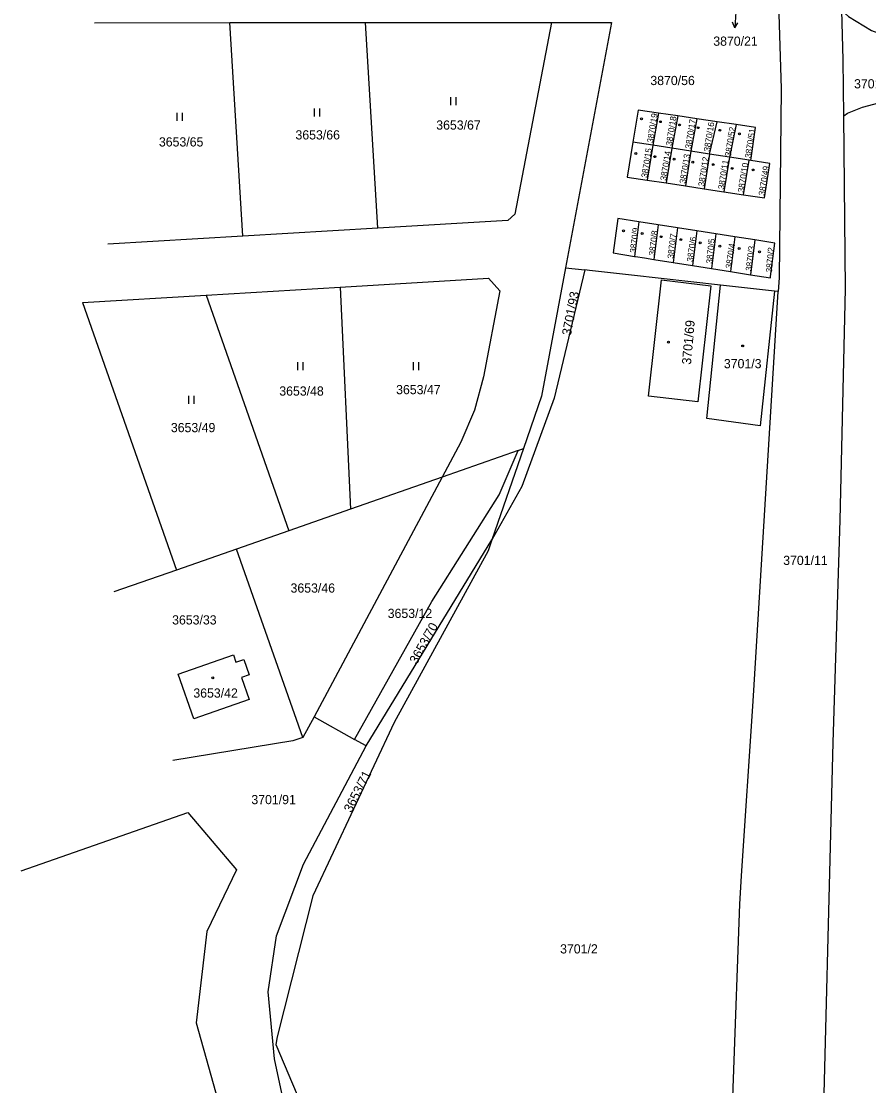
# Model space of a CAD drawing. Extents: x -527335 to -526256, y -1079142 to -1077836.
# Drawn here: x -527299.2 to -527142.6, y -1078182.5 to -1077985.7 of the extents above; entities that cross this region are included whole.
import ezdxf

# ---------------------------------------------------------------- set-up
doc = ezdxf.new("R2010")
doc.units = 0
for name, color, linetype in [('Hranice parcel', 7, 'Continuous'), ('Parcelní čísla', 7, 'Continuous'), ('Pop  PČ popisy', 7, 'Continuous'), ('Značky budov', 7, 'Continuous'), ('Značky kultur', 7, 'Continuous')]:
    doc.layers.add(name, color=color, linetype=linetype)

msp = doc.modelspace()

# ---------------------------------------------------------------- linework, layer by layer
at = {"layer": 'Hranice parcel'}
for p, q in [((-527285.69, -1077985.99), (-527260.64, -1077985.98)), ((-527260.64, -1077985.98), (-527235.6, -1077985.97)), ((-527258.27, -1078025.45), (-527260.64, -1077985.98)), ((-527235.6, -1077985.97), (-527201.2, -1077985.95)), ((-527233.32, -1078023.96), (-527235.6, -1077985.97)), ((-527201.2, -1077985.95), (-527208.02, -1078021.38)), ((-527201.2, -1077985.95), (-527190.13, -1077985.95)), ((-527190.13, -1077985.95), (-527198.62, -1078031.28)), ((-527181.44, -1078002.7), (-527182.49, -1078008.63)), ((-527177.88, -1078003.23), (-527181.44, -1078002.7)), ((-527177.88, -1078003.23), (-527179, -1078009.17)), ((-527174.36, -1078003.75), (-527177.88, -1078003.23)), ((-527174.36, -1078003.75), (-527175.45, -1078009.72)), ((-527170.64, -1078004.32), (-527174.36, -1078003.75)), ((-527172, -1078010.26), (-527170.64, -1078004.32)), ((-527167.08, -1078004.82), (-527170.64, -1078004.32)), ((-527167.08, -1078004.82), (-527168.36, -1078010.83)), ((-527182.49, -1078008.63), (-527186.19, -1078008.06)), ((-527182.49, -1078008.63), (-527183.55, -1078015.08)), ((-527179, -1078009.17), (-527182.49, -1078008.63)), ((-527179, -1078009.17), (-527180.04, -1078015.61)), ((-527175.45, -1078009.72), (-527179, -1078009.17)), ((-527175.45, -1078009.72), (-527176.48, -1078016.15)), ((-527172, -1078010.26), (-527175.45, -1078009.72)), ((-527172, -1078010.26), (-527173.03, -1078016.68)), ((-527168.36, -1078010.83), (-527172, -1078010.26)), ((-527168.36, -1078010.83), (-527169.37, -1078017.23)), ((-527164.72, -1078011.39), (-527168.36, -1078010.83)), ((-527165.72, -1078017.79), (-527164.72, -1078011.39)), ((-527164.4, -1078011.44), (-527164.72, -1078011.39)), ((-527183.55, -1078015.08), (-527180.04, -1078015.61)), ((-527180.04, -1078015.61), (-527176.48, -1078016.15)), ((-527176.48, -1078016.15), (-527173.03, -1078016.68)), ((-527173.03, -1078016.68), (-527169.37, -1078017.23)), ((-527169.37, -1078017.23), (-527165.72, -1078017.79)), ((-527185.08, -1078022.81), (-527185.88, -1078029.17)), ((-527181.52, -1078023.36), (-527185.08, -1078022.81)), ((-527233.32, -1078023.96), (-527258.27, -1078025.45)), ((-527181.52, -1078023.36), (-527182.33, -1078029.74)), ((-527177.96, -1078023.92), (-527181.52, -1078023.36)), ((-527177.96, -1078023.92), (-527178.77, -1078030.3)), ((-527174.39, -1078024.47), (-527177.96, -1078023.92)), ((-527174.39, -1078024.47), (-527175.2, -1078030.87)), ((-527170.84, -1078025.02), (-527174.39, -1078024.47)), ((-527170.84, -1078025.02), (-527171.65, -1078031.43)), ((-527167.33, -1078025.57), (-527170.84, -1078025.02)), ((-527258.27, -1078025.45), (-527283.23, -1078026.95)), ((-527167.33, -1078025.57), (-527168.15, -1078031.98)), ((-527163.67, -1078026.14), (-527167.33, -1078025.57)), ((-527163.67, -1078026.14), (-527164.48, -1078032.56)), ((-527182.33, -1078029.74), (-527178.77, -1078030.3)), ((-527178.77, -1078030.3), (-527175.2, -1078030.87)), ((-527175.2, -1078030.87), (-527171.65, -1078031.43)), ((-527198.62, -1078031.28), (-527195.06, -1078031.68)), ((-527171.65, -1078031.43), (-527168.15, -1078031.98)), ((-527168.15, -1078031.98), (-527164.48, -1078032.56)), ((-527265.02, -1078036.33), (-527240.25, -1078034.84)), ((-527240.25, -1078034.84), (-527238.34, -1078075.88)), ((-527160.02, -1078035.61), (-527169.98, -1078034.5)), ((-527287.85, -1078037.7), (-527265.02, -1078036.33)), ((-527265.02, -1078036.33), (-527249.76, -1078079.88)), ((-527159.33, -1078035.65), (-527160.02, -1078035.61)), ((-527287.85, -1078037.7), (-527270.53, -1078087.15)), ((-527207.36, -1078065.03), (-527221.44, -1078069.96)), ((-527206.41, -1078064.7), (-527212.24, -1078081.56)), ((-527207.36, -1078065.03), (-527206.41, -1078064.7)), ((-527221.44, -1078069.96), (-527245.09, -1078114.25)), ((-527221.44, -1078069.96), (-527238.34, -1078075.88)), ((-527238.34, -1078075.88), (-527249.76, -1078079.88)), ((-527249.76, -1078079.88), (-527259.42, -1078083.26)), ((-527235.46, -1078119.66), (-527212.24, -1078081.56)), ((-527259.42, -1078083.26), (-527270.53, -1078087.15)), ((-527247.2, -1078118.08), (-527259.42, -1078083.26)), ((-527270.53, -1078087.15), (-527282.07, -1078091.19)), ((-527245.09, -1078114.25), (-527247.2, -1078118.08)), ((-527245.09, -1078114.25), (-527237.62, -1078118.45)), ((-527235.46, -1078119.66), (-527237.62, -1078118.45))]:
    msp.add_line(p, q, dxfattribs=at)
for points in [[(-527161.57, -1077909.37), (-527158.79, -1077998.21), (-527159.18, -1078033.14), (-527159.33, -1078035.65)], [(-527147.58, -1077983.71), (-527146.35, -1077984.82), (-527142.07, -1077987.45), (-527140.94, -1077987.84)], [(-527147.21, -1078003.19), (-527147.31, -1077992.85), (-527147.58, -1077983.71)], [(-527147.21, -1078003.19), (-527146.56, -1078002.73), (-527143.75, -1078001.6), (-527140.75, -1078000.83), (-527135, -1078001.05)], [(-527181.44, -1078002.7), (-527185.21, -1078002.14), (-527186.19, -1078008.06)], [(-527151.32, -1078203.19), (-527149.15, -1078119.04), (-527147.89, -1078077.9), (-527146.9, -1078035.16), (-527147.21, -1078003.19)], [(-527164.4, -1078011.44), (-527163.51, -1078005.35), (-527167.08, -1078004.82)], [(-527186.19, -1078008.06), (-527187.25, -1078014.51), (-527183.55, -1078015.08)], [(-527165.72, -1078017.79), (-527161.87, -1078018.37), (-527160.88, -1078011.99), (-527164.4, -1078011.44)], [(-527208.02, -1078021.38), (-527209.32, -1078022.52), (-527233.32, -1078023.96)], [(-527185.08, -1078022.81), (-527188.98, -1078022.2), (-527189.82, -1078028.55), (-527185.88, -1078029.17)], [(-527164.48, -1078032.56), (-527160.77, -1078033.15), (-527160.74, -1078032.91), (-527159.95, -1078026.72), (-527163.67, -1078026.14)], [(-527185.88, -1078029.17), (-527185.7, -1078029.2), (-527184.06, -1078029.46), (-527182.33, -1078029.74)], [(-527195.06, -1078031.68), (-527200.73, -1078055.36), (-527206.71, -1078071.69), (-527212.24, -1078081.56)], [(-527198.62, -1078031.28), (-527203.07, -1078055.03), (-527206.41, -1078064.7)], [(-527169.98, -1078034.5), (-527186.45, -1078032.65), (-527194.19, -1078031.78), (-527195.06, -1078031.68)], [(-527240.25, -1078034.84), (-527212.84, -1078033.2), (-527210.76, -1078035.57), (-527213.81, -1078051.42), (-527215.47, -1078057.62), (-527217.99, -1078063.51), (-527221.44, -1078069.96)], [(-527174.21, -1078056.09), (-527183.27, -1078055.01), (-527180.87, -1078033.51), (-527171.77, -1078034.65), (-527174.21, -1078056.09)], [(-527160.02, -1078035.61), (-527162.69, -1078060.52), (-527172.55, -1078059.14), (-527169.98, -1078034.5)], [(-527168.74, -1078213.47), (-527166.4, -1078148.92), (-527166.12, -1078143.69), (-527163.93, -1078111.36), (-527159.33, -1078035.65)], [(-527237.62, -1078118.45), (-527223.31, -1078092.99), (-527210.88, -1078073.22), (-527207.36, -1078065.03)], [(-527212.24, -1078081.56), (-527212.93, -1078083.57), (-527230.3, -1078115.32), (-527245.35, -1078147.39), (-527251.94, -1078173.41), (-527252.16, -1078174.82), (-527241.36, -1078200.26)], [(-527259.52, -1078104.18), (-527258.06, -1078103.68), (-527257.08, -1078106.5), (-527258.53, -1078107.01), (-527257.1, -1078111.09), (-527267.32, -1078114.66), (-527270.18, -1078106.38), (-527259.99, -1078102.83), (-527259.52, -1078104.18)], [(-527247.2, -1078118.08), (-527249.02, -1078118.69), (-527271.16, -1078122.34)], [(-527247.79, -1078199.08), (-527252.39, -1078177.49), (-527253.58, -1078165.1), (-527252.03, -1078154.75), (-527247.04, -1078141.51), (-527235.46, -1078119.66)], [(-527299.19, -1078142.76), (-527268.42, -1078131.98), (-527259.44, -1078142.54), (-527264.92, -1078153.96), (-527266.9, -1078170.85), (-527258.33, -1078201.37)]]:
    msp.add_lwpolyline(points, dxfattribs=at)
at = {"layer": 'Pop  PČ popisy'}
for p, q in [((-527167.14, -1077983.96), (-527167.35, -1077986.95)), ((-527167.35, -1077986.95), (-527167.78, -1077985.92)), ((-527167.35, -1077986.95), (-527166.78, -1077985.99))]:
    msp.add_line(p, q, dxfattribs=at)
at = {"layer": 'Značky budov'}
for centre in [(-527184.6, -1078003.77), (-527181.11, -1078004.29), (-527177.57, -1078004.89), (-527174.11, -1078005.4), (-527170.14, -1078005.88), (-527166.51, -1078006.54), (-527185.66, -1078010.18), (-527182.15, -1078010.75), (-527178.58, -1078011.21), (-527175.13, -1078011.76), (-527171.33, -1078012.22), (-527167.83, -1078012.91), (-527163.94, -1078013.21), (-527187.93, -1078024.45), (-527184.45, -1078024.94), (-527180.98, -1078025.54), (-527177.33, -1078026.08), (-527173.73, -1078026.69), (-527170.13, -1078027.3), (-527166.53, -1078027.74), (-527162.77, -1078028.34), (-527179.63, -1078045.03), (-527165.9, -1078045.74), (-527263.82, -1078107.05)]:
    msp.add_circle(centre, 0.175, dxfattribs=at)
at = {"layer": 'Značky kultur'}
for p, q in [((-527219.85, -1078001.23), (-527219.85, -1077999.73)), ((-527218.85, -1078001.23), (-527218.85, -1077999.73)), ((-527270.41, -1078004.15), (-527270.41, -1078002.65)), ((-527269.41, -1078004.15), (-527269.41, -1078002.65)), ((-527245, -1078003.35), (-527245, -1078001.85)), ((-527244, -1078003.35), (-527244, -1078001.85)), ((-527248.11, -1078050.21), (-527248.11, -1078048.71)), ((-527247.11, -1078050.21), (-527247.11, -1078048.71)), ((-527226.73, -1078050.21), (-527226.73, -1078048.71)), ((-527225.73, -1078050.21), (-527225.73, -1078048.71)), ((-527268.23, -1078056.43), (-527268.23, -1078054.93)), ((-527267.23, -1078056.43), (-527267.23, -1078054.93))]:
    msp.add_line(p, q, dxfattribs=at)

# ---------------------------------------------------------------- texts
at = {"layer": 'Parcelní čísla'}
for s, p in [('3870/21', (-527171.33, -1077990.25)), ('3870/56', (-527182.96, -1077997.52)), ('3701/51', (-527145.32, -1077998.13)), ('3653/67', (-527222.52, -1078005.75)), ('3653/65', (-527273.76, -1078008.87)), ('3653/66', (-527248.53, -1078007.57)), ('3701/3', (-527169.37, -1078049.85)), ('3653/48', (-527251.52, -1078054.91)), ('3653/47', (-527229.93, -1078054.65)), ('3653/49', (-527271.55, -1078061.67)), ('3701/11', (-527158.41, -1078086.21)), ('3653/46', (-527249.44, -1078091.32)), ('3653/33', (-527271.32, -1078097.21)), ('3653/12', (-527231.49, -1078096.01)), ('3653/42', (-527267.4, -1078110.73)), ('3701/91', (-527256.68, -1078130.42)), ('3701/2', (-527199.63, -1078158.01))]:
    msp.add_text(s, height=1.7, dxfattribs=at).set_placement(p)
for s, height, rotation, p in [('3870/19', 1.14, 81, (-527182.47, -1078008.27)), ('3870/18', 1.14, 81, (-527178.98, -1078008.81)), ('3870/17', 1.14, 81, (-527175.43, -1078009.36)), ('3870/16', 1.14, 81, (-527171.98, -1078009.9)), ('3870/52', 1.14, 81, (-527168.07, -1078010.79)), ('3870/51', 1.14, 81, (-527164.38, -1078011.08)), ('3870/15', 1.14, 81, (-527183.53, -1078014.72)), ('3870/14', 1.14, 81, (-527180.02, -1078015.25)), ('3870/13', 1.14, 81, (-527176.46, -1078015.79)), ('3870/12', 1.14, 81, (-527173.01, -1078016.32)), ('3870/11', 1.14, 81, (-527169.35, -1078016.87)), ('3870/10', 1.14, 81, (-527165.7, -1078017.43)), ('3870/49', 1.14, 81, (-527161.85, -1078018.01)), ('3870/9', 1.14, 83, (-527185.65, -1078028.59)), ('3870/8', 1.14, 83, (-527182.14, -1078029.09)), ('3870/7', 1.14, 83, (-527178.69, -1078029.65)), ('3870/6', 1.14, 82, (-527175.1, -1078030.25)), ('3870/5', 1.139, 84, (-527171.53, -1078030.58)), ('3870/4', 1.14, 82, (-527167.94, -1078031.49)), ('3870/3', 1.14, 83, (-527164.24, -1078031.95)), ('3870/2', 1.139, 85, (-527160.49, -1078032.2)), ('3701/93', 1.7, 79, (-527197.66, -1078043.91)), ('3701/69', 1.7, 85, (-527175.45, -1078049.23)), ('3653/70', 1.7, 61, (-527226.1, -1078104.67)), ('3653/71', 1.7, 63, (-527238.2, -1078132.1))]:
    msp.add_text(s, height=height, rotation=rotation, dxfattribs=at).set_placement(p)

doc.saveas('drawing.dxf')
